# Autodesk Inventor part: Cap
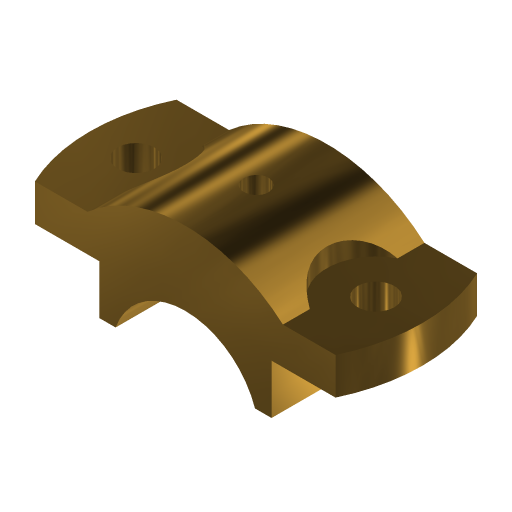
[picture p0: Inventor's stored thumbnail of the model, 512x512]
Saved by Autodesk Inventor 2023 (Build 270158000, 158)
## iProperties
Created: 2009-04
Part Number: Cap
Document SubType Name: Modeling
Designer: Sham
Density: 8.47 g/cm^3
Material: Brass, Soft Yellow
Appearance: Brass - Satin
Author: Sham
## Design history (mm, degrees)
sketch "Sketch1"
  geometry: L1 (-48.857, 23)-(48.857, 23); L2 (48.857, -23)-(-48.857, -23); A1 r 54 centre (0, 0) between (-48.857, 23) and (-48.857, -23); A2 r 54 centre (0, 0) between (48.857, -23) and (48.857, 23); 1 further point
  constraints: 4 end point, 4 point on circle, 2 centre point, 2 coincident, 1 horizontal, 1 parallel, 1 other
  dimensions: "d3" = 54 radius of A1; "d4" = 54 radius of A2; "d5" = 46 distance between parallel lines of L2 L1; "d6" = 23 distance from line of point (0, 0) L1
extrude "Extrusion1" new body sketch "Sketch1" distance "d7" = 12; taper "d8" = 0 deg
sketch "Sketch3"
  geometry: L1 (20.906, 0)-(20.906, -16); L2 (76.906, -0.137)-(76.906, -16.137); L3 (20.906, -16)-(26.23, -16); L4 (71.532, -16.137)-(76.906, -16.137); L5 (76.906, -0.137)-(76.857, 12); L6 (97.714, 0)-(0, 0) reference; L7 (76.857, 12)-(80.606, 12); L8 (17.108, 12)-(20.906, 12); L9 (20.906, 12)-(20.906, 0); L10 (0, 12)-(97.714, 12) reference; A1 r 24 centre (48.857, -24) between (71.532, -16.137) and (26.23, -16); A2 r 48 centre (48.857, -24) between (80.606, 12) and (17.108, 12); 3 further points
  constraints: 16 end point, 4 point on circle, 3 parallel, 3 perpendicular, 2 centre point, 2 coincident, 2 vertical alignment, 1 collinear, 1 midpoint, 1 vertical, 2 other
  dimensions: "d17" = 48 diameter of A1; "d18" = 16 distance of L1.start L1.end; "d19" = 56 distance between parallel lines of L2 L1; "d21" = 8 vertical distance of A1.centre L1.end; "d22" = 48 radius of A2; "d23" = 0 distance from line of L6 L1.start; "d38" = 31.74902 distance of L7.end point (48.857, 12); "d39" = 28 distance from line of point (48.857, 12) L5
extrude "Extrusion2" join sketch "Sketch3" stored distance "d24" = 12; taper "d25" = 0 deg
sketch "Sketch4"
  geometry: 2 further points
  dimensions: "d26" = 78 distance of point (39, 0) point (-39, 0)
hole "Hole1" sketch "Sketch4" at (-39, 0), (39, 0) diameter "d28" = 12; stored, may be unused: countersink angle "d32" = 90 deg, drill point angle "d34" = 118 deg; dims "d29" = 6, "d30" = 4, "d31" = 2, "d33" = 8
sketch "Sketch5"
  geometry: L1 (-31.749, -23)-(-31.749, 23) reference; L2 (-31.749, 14.263)-(-31.749, -14.263); C1 r 6 at (-39, 0) reference; A1 r 16 centre (-39, 0) between (-31.749, -14.263) and (-31.749, 14.263)
  constraints: 2 end point, 2 point on circle, 1 centre point, 1 coincident, 1 collinear, 1 point on line
  dimensions: "d35" = 16 radius of A1
extrude "Extrusion3" cut sketch "Sketch5" distance "d36" = 12; taper "d37" = 0 deg
mirror "Mirror2"
workplane "Work Plane4"
sketch "Sketch6"
  geometry: L1 (-31.749, 0)-(31.749, 0) reference; 1 further point
  dimensions: "d40" = 23 distance from line of L1 point (0, 23)
hole "Hole2" sketch "Sketch6" at (0, 23) diameter "d41" = 6; stored, may be unused: countersink angle "d45" = 90 deg, drill point angle "d47" = 118 deg; dims "d42" = 6, "d43" = 8, "d44" = 16, "d46" = 8
body "Solid1"
